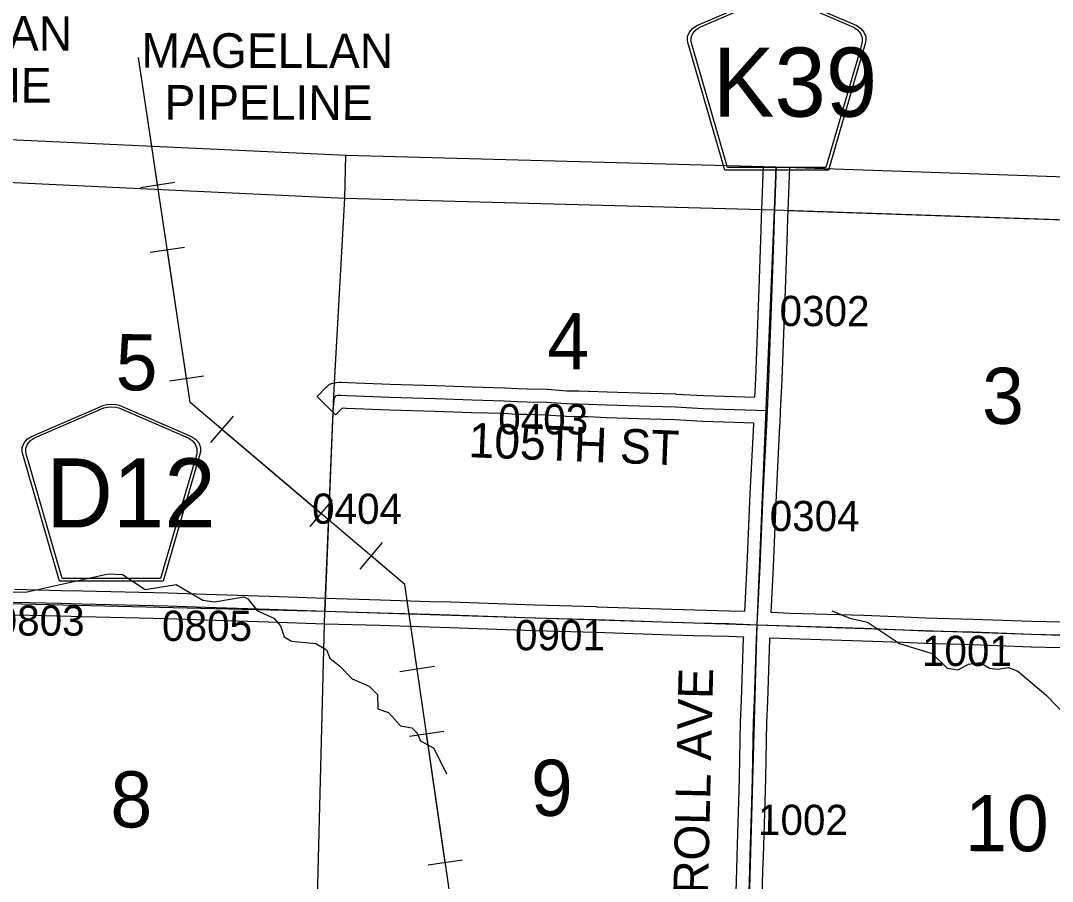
# Model space of a CAD drawing. Extents: x -157.2 to -99.3, y 12.2 to 46.2.
# Drawn here: x -143.15 to -140.761, y 39.474 to 41.468 of the extents above; entities that cross this region are included whole.
import ezdxf

# ---------------------------------------------------------------- set-up
doc = ezdxf.new("R2010")
doc.units = 0
for name, color, linetype in [('tdCoClipBndry', 7, 'Continuous'), ('tdCoCoBndry', 7, 'Continuous'), ('tdCoCoBndryPart', 7, 'Continuous'), ('tdCoHydroRiver', 7, 'Continuous'), ('tdCoPipe', 7, 'Continuous'), ('tdCoPipeTxt', 7, 'Continuous'), ('tdCoSecRdNmbr', 7, 'Continuous'), ('tdCoSecRdTxt', 7, 'Continuous'), ('tdCoSecRteBand', 7, 'Continuous'), ('tdCoSecRteCL', 7, 'Continuous'), ('tdCoSectLine', 7, 'Continuous'), ('tdCoSectLinePart', 7, 'Continuous'), ('tdCoSectNmbr', 7, 'Continuous'), ('tdCoShieldCoRte', 7, 'Continuous'), ('tdCoShieldCoRteHrd', 7, 'Continuous'), ('tdCoSurfAsphalt', 7, 'Continuous'), ('tdCoSurfGravel', 7, 'Continuous'), ('tdCoSurfLNO', 7, 'Continuous'), ('tdCoTwpBndryShd', 7, 'Continuous')]:
    doc.layers.add(name, color=color, linetype=linetype)

msp = doc.modelspace()

# ---------------------------------------------------------------- linework, layer by layer
at = {"layer": 'tdCoClipBndry'}
msp.add_lwpolyline([(-150.407, 41.4676), (-149.3946, 41.4438), (-148.3968, 41.411), (-147.4001, 41.3615), (-145.4135, 41.2969), (-142.396, 41.1563), (-141.4008, 41.1294), (-139.4104, 41.0607), (-138.4128, 41.0377), (-137.3849, 40.9986), (-130.3617, 40.7621)], dxfattribs=at)
at = {"layer": 'tdCoCoBndry'}
msp.add_lwpolyline([(-152.9518, 41.3883), (-152.409, 41.3796), (-151.4143, 41.374), (-150.4076, 41.3676), (-149.397, 41.3439), (-148.4001, 41.3111), (-147.4042, 41.2616), (-146.4159, 41.2271), (-145.4182, 41.197), (-144.4306, 41.151), (-143.3778, 41.1032), (-142.3996, 41.0564), (-141.4043, 41.0295), (-140.4086, 40.9954), (-139.4133, 40.9608), (-138.4166, 40.9378), (-137.3885, 40.8986), (-136.3904, 40.8656), (-135.3934, 40.8324), (-134.3958, 40.7988)], dxfattribs=at)
at = {"layer": 'tdCoCoBndryPart'}
for points in [[(-143.6171, 41.1141), (-143.3778, 41.1032), (-142.3996, 41.0564), (-141.4341, 41.0303)], [(-141.3742, 41.0285), (-140.4385, 40.9964)]]:
    msp.add_lwpolyline(points, dxfattribs=at)
at = {"layer": 'tdCoHydroRiver'}
for points in [[(-143.2296, 40.1435), (-143.1349, 40.1451), (-142.9472, 40.1863), (-142.9141, 40.1852), (-142.8616, 40.1504), (-142.7901, 40.1622), (-142.7282, 40.1255), (-142.7015, 40.1214), (-142.6332, 40.1334), (-142.6239, 40.1284), (-142.6012, 40.1008), (-142.5638, 40.0838), (-142.5487, 40.0659), (-142.54, 40.0404), (-142.523, 40.0304), (-142.4663, 40.0254), (-142.4416, 40.0103), (-142.4343, 39.9912), (-142.4112, 39.9731), (-142.3822, 39.9437), (-142.3433, 39.9266), (-142.3234, 39.9071), (-142.323, 39.8739), (-142.298, 39.8652), (-142.2706, 39.8343), (-142.2439, 39.8303), (-142.2317, 39.8173), (-142.2244, 39.7997), (-142.1934, 39.7829), (-142.1638, 39.7235)], [(-141.2719, 40.1013), (-141.2299, 40.0841), (-141.1892, 40.0749), (-141.115, 40.0251), (-141.04, 40.0022), (-141.0048, 39.9679), (-140.9797, 39.9639), (-140.9556, 39.9773), (-140.9286, 39.9811), (-140.907, 39.9678), (-140.8881, 39.9656), (-140.8627, 39.9695), (-140.8409, 39.9609), (-140.7764, 39.9067), (-140.7275, 39.8562)]]:
    msp.add_lwpolyline(points, dxfattribs=at)
at = {"layer": 'tdCoPipe'}
for p, q in [((-142.793, 41.0928), (-142.8725, 41.0809)), ((-142.7705, 40.9425), (-142.8501, 40.9306)), ((-142.7259, 40.6448), (-142.8054, 40.6329)), ((-142.6582, 40.5521), (-142.7103, 40.4906)), ((-142.4286, 40.3575), (-142.4807, 40.2961)), ((-142.3127, 40.2592), (-142.3648, 40.1977)), ((-142.1921, 39.9716), (-142.2717, 39.96)), ((-142.1703, 39.8211), (-142.25, 39.8095)), ((-142.127, 39.5233), (-142.2066, 39.5117))]:
    msp.add_line(p, q, dxfattribs=at)
for points in [[(-136.934, 22.5495), (-137.7242, 24.8933), (-138.4968, 27.1666), (-138.4114, 27.2635), (-138.4614, 27.8735), (-138.7227, 28.0895), (-138.7183, 28.4663), (-139.0397, 29.2926), (-139.1184, 29.8198), (-140.0614, 32.629), (-140.3902, 33.7747), (-140.3873, 34.3489), (-140.6033, 34.3601), (-141.0238, 35.5765), (-141.1818, 36.0085), (-141.3937, 37.236), (-141.4233, 37.6118), (-141.6227, 37.7022), (-142.0941, 39.016), (-142.2605, 40.1621), (-142.7574, 40.5833), (-142.8772, 41.3829)], [(-142.8328, 41.0869), (-142.8509, 41.2078)], [(-142.7657, 40.6389), (-142.8103, 40.9365)], [(-142.4547, 40.3267), (-142.6843, 40.5213)], [(-142.232, 39.9658), (-142.2605, 40.1621), (-142.3387, 40.2284)], [(-142.1669, 39.5175), (-142.2101, 39.8153)]]:
    msp.add_lwpolyline(points, dxfattribs=at)
at = {"layer": 'tdCoSecRteBand'}
for points in [[(-143.163, 40.151), (-143.0561, 40.1483), (-143.0072, 40.1471), (-142.8085, 40.1424), (-142.8083, 40.1424), (-142.8081, 40.1424), (-142.7211, 40.1394), (-142.5742, 40.135), (-142.5741, 40.135), (-142.574, 40.135), (-142.4438, 40.1301), (-142.3169, 40.1266), (-142.3168, 40.1266), (-142.3167, 40.1266), (-142.2018, 40.1229), (-142.1545, 40.1214), (-142.1544, 40.1214), (-142.1543, 40.1214), (-141.9594, 40.1145), (-141.817, 40.1106), (-141.8169, 40.1106), (-141.8168, 40.1105), (-141.6422, 40.1046), (-141.5901, 40.1029), (-141.5099, 40.1012), (-141.5096, 40.1012), (-141.5094, 40.1012), (-141.4733, 40.0998), (-141.4733, 40.1), (-141.4726, 40.1147), (-141.4726, 40.1148), (-141.4726, 40.1149), (-141.4679, 40.206), (-141.4608, 40.3718), (-141.4608, 40.372), (-141.4608, 40.3721), (-141.4527, 40.533), (-141.4525, 40.5357), (-141.4985, 40.537), (-141.4986, 40.537), (-141.4987, 40.537), (-141.5705, 40.5398), (-141.5707, 40.5398), (-141.571, 40.5398), (-141.6352, 40.5432), (-141.6939, 40.5447), (-141.6941, 40.5447), (-141.6942, 40.5447), (-141.7938, 40.5481), (-141.7939, 40.5481), (-141.794, 40.5481), (-141.8362, 40.5499), (-141.8587, 40.5501), (-141.859, 40.5501), (-141.8592, 40.5501), (-141.8873, 40.5508), (-141.888, 40.5509), (-141.8886, 40.5509), (-141.9338, 40.5541), (-141.979, 40.5553), (-142.0004, 40.5558), (-142.001, 40.5558), (-142.0016, 40.5558), (-142.0316, 40.5578), (-142.1055, 40.5595), (-142.1057, 40.5595), (-142.1059, 40.5595), (-142.1904, 40.5627), (-142.296, 40.5659), (-142.2962, 40.5659), (-142.2963, 40.5659), (-142.3954, 40.5696), (-142.3961, 40.5696), (-142.3967, 40.5697), (-142.4057, 40.5704), (-142.4211, 40.555), (-142.4635, 40.5974), (-142.4423, 40.6186), (-142.4404, 40.6205), (-142.4348, 40.6262), (-142.4271, 40.6283), (-142.4244, 40.629), (-142.422, 40.6297), (-142.4196, 40.6299), (-142.4124, 40.6307), (-142.4096, 40.6309), (-142.4069, 40.6307), (-142.3925, 40.6295), (-142.2941, 40.6259), (-142.1884, 40.6227), (-142.1883, 40.6227), (-142.1882, 40.6227), (-142.1038, 40.6195), (-142.0296, 40.6177), (-142.029, 40.6177), (-142.0284, 40.6177), (-141.9984, 40.6157), (-141.9776, 40.6153), (-141.9775, 40.6153), (-141.9774, 40.6153), (-141.9316, 40.614), (-141.9309, 40.614), (-141.9303, 40.614), (-141.8851, 40.6108), (-141.8578, 40.6101), (-141.8351, 40.6098), (-141.8347, 40.6098), (-141.8343, 40.6098), (-141.7917, 40.6081), (-141.6923, 40.6047), (-141.6332, 40.6032), (-141.6328, 40.6032), (-141.6324, 40.6031), (-141.568, 40.5997), (-141.4966, 40.597), (-141.4499, 40.5957), (-141.4499, 40.5961), (-141.448, 40.6391), (-141.4448, 40.7228), (-141.4402, 40.8476), (-141.4352, 40.9825), (-141.4345, 41.0135), (-141.4345, 41.0137), (-141.4345, 41.0139), (-141.4339, 41.0307), (-141.4302, 41.1302)], [(-141.3702, 41.1283), (-141.3739, 41.0285), (-141.3745, 41.0119), (-141.3753, 40.9809), (-141.3753, 40.9807), (-141.3753, 40.9805), (-141.3802, 40.8454), (-141.3802, 40.8454), (-141.3802, 40.8454), (-141.3848, 40.7206), (-141.3848, 40.7206), (-141.3848, 40.7206), (-141.388, 40.6367), (-141.388, 40.6366), (-141.388, 40.6366), (-141.3912, 40.5637), (-141.3921, 40.534), (-141.3925, 40.534), (-141.3927, 40.5303), (-141.3927, 40.5302), (-141.3927, 40.5301), (-141.4009, 40.3691), (-141.408, 40.2033), (-141.408, 40.2032), (-141.408, 40.203), (-141.4127, 40.1119), (-141.4133, 40.0975), (-141.368, 40.0958), (-141.198, 40.0908), (-141.1978, 40.0908), (-141.1976, 40.0908), (-141.1054, 40.0871), (-141.1053, 40.0871), (-141.1053, 40.0871), (-141.0547, 40.0849), (-140.945, 40.0819), (-140.9448, 40.0819), (-140.9447, 40.0819), (-140.809, 40.0768), (-140.6746, 40.0736)], [(-141.4966, 39.3458), (-141.4921, 39.5016), (-141.4921, 39.5018), (-141.4921, 39.5019), (-141.4909, 39.5338), (-141.4865, 39.6856), (-141.4857, 39.7145), (-141.483, 39.8437), (-141.483, 39.844), (-141.483, 39.8442), (-141.481, 39.894), (-141.4761, 40.0374), (-141.4761, 40.0376), (-141.4761, 40.0377), (-141.476, 40.0398), (-141.5114, 40.0412), (-141.5916, 40.0429), (-141.5917, 40.0429), (-141.5919, 40.0429), (-141.6442, 40.0447), (-141.6442, 40.0447), (-141.6442, 40.0447), (-141.8187, 40.0506), (-141.9612, 40.0545), (-141.9613, 40.0545), (-141.9614, 40.0545), (-142.1564, 40.0614), (-142.2037, 40.0629), (-142.2037, 40.0629), (-142.2037, 40.0629), (-142.3186, 40.0666), (-142.4456, 40.0701), (-142.4457, 40.0701), (-142.4459, 40.0701), (-142.5761, 40.075), (-142.723, 40.0794), (-142.7231, 40.0794), (-142.7231, 40.0794), (-142.81, 40.0824), (-143.0086, 40.0871), (-143.0087, 40.0871), (-143.0087, 40.0871), (-143.0576, 40.0883), (-143.1644, 40.091)], [(-140.6763, 40.0136), (-140.8106, 40.0168), (-140.8109, 40.0168), (-140.8111, 40.0168), (-140.9468, 40.022), (-141.0566, 40.0249), (-141.0568, 40.0249), (-141.0571, 40.0249), (-141.1078, 40.0272), (-141.1999, 40.0309), (-141.3698, 40.0358), (-141.37, 40.0358), (-141.3701, 40.0358), (-141.4158, 40.0375), (-141.416, 40.0375), (-141.4161, 40.0352), (-141.4211, 39.8918), (-141.4211, 39.8918), (-141.4211, 39.8917), (-141.423, 39.8422), (-141.4257, 39.7132), (-141.4257, 39.7131), (-141.4257, 39.7131), (-141.4265, 39.684), (-141.4265, 39.6839), (-141.4265, 39.6839), (-141.4309, 39.532), (-141.4309, 39.5318), (-141.4309, 39.5317), (-141.4322, 39.4998), (-141.4366, 39.3442)]]:
    msp.add_lwpolyline(points, dxfattribs=at)
at = {"layer": 'tdCoSecRteCL'}
for points in [[(-141.4212, 40.5648), (-141.418, 40.6379), (-141.4148, 40.7217), (-141.4102, 40.8465), (-141.4053, 40.9816), (-141.4045, 41.0128), (-141.4039, 41.0296), (-141.4002, 41.1294)], [(-142.4211, 40.5974), (-142.4192, 40.5993), (-142.4165, 40.6001), (-142.4093, 40.6008), (-142.3943, 40.5996), (-142.2951, 40.5959), (-142.1893, 40.5927), (-142.1048, 40.5895), (-142.0303, 40.5877), (-141.9997, 40.5858), (-141.9783, 40.5853), (-141.9324, 40.584), (-141.8865, 40.5808), (-141.8584, 40.5801), (-141.8355, 40.5798), (-141.7928, 40.5781), (-141.6932, 40.5747), (-141.634, 40.5732), (-141.5694, 40.5697), (-141.4976, 40.567), (-141.4212, 40.5648)], [(-141.4447, 40.0687), (-141.4427, 40.1133), (-141.438, 40.2046), (-141.4308, 40.3706), (-141.4227, 40.5316), (-141.4212, 40.5648)], [(-143.685, 40.1302), (-143.6617, 40.1294), (-143.5707, 40.1284), (-143.4535, 40.1245), (-143.3527, 40.1222), (-143.2772, 40.1227), (-143.1638, 40.121), (-143.0569, 40.1183), (-143.0079, 40.1171), (-142.8092, 40.1124), (-142.7221, 40.1094), (-142.5751, 40.105), (-142.4447, 40.1001), (-142.3177, 40.0966), (-142.2028, 40.0929), (-142.1554, 40.0914), (-141.9603, 40.0845), (-141.8178, 40.0806), (-141.6432, 40.0746), (-141.5909, 40.0729), (-141.5105, 40.0712), (-141.4447, 40.0687)], [(-141.472, 39.0694), (-141.4705, 39.1449), (-141.4695, 39.2088), (-141.4666, 39.3449), (-141.4621, 39.5008), (-141.4609, 39.5328), (-141.4565, 39.6847), (-141.4557, 39.7138), (-141.453, 39.8431), (-141.451, 39.8929), (-141.4461, 40.0364), (-141.4447, 40.0687)], [(-141.4447, 40.0687), (-141.369, 40.0658), (-141.1988, 40.0608), (-141.1066, 40.0571), (-141.0558, 40.0549), (-140.9458, 40.052), (-140.8099, 40.0468), (-140.6753, 40.0436), (-140.5855, 40.0394), (-140.5108, 40.0362), (-140.4583, 40.0344), (-140.4469, 40.0343)]]:
    msp.add_lwpolyline(points, dxfattribs=at)
at = {"layer": 'tdCoSectLine'}
for points in [[(-142.3996, 41.0564), (-142.3967, 41.1563)], [(-141.4043, 41.0295), (-141.4005, 41.1294)], [(-143.3778, 41.1032), (-142.3996, 41.0564)], [(-142.4455, 40.1001), (-142.425, 40.6004), (-142.3996, 41.0564)], [(-142.3996, 41.0564), (-141.4043, 41.0295)], [(-141.445, 40.0687), (-141.4043, 41.0295)], [(-141.4043, 41.0295), (-140.4086, 40.9954)], [(-143.4354, 40.1241), (-142.4455, 40.1001)], [(-142.4709, 39.1056), (-142.4455, 40.1001)], [(-142.4455, 40.1001), (-141.445, 40.0687)], [(-141.4724, 39.0694), (-141.445, 40.0687)], [(-141.445, 40.0687), (-140.4473, 40.0343)]]:
    msp.add_lwpolyline(points, dxfattribs=at)
at = {"layer": 'tdCoSectLinePart'}
for points in [[(-142.3996, 41.0564), (-142.3967, 41.1563)], [(-143.3778, 41.1032), (-142.3996, 41.0564)], [(-142.4234, 40.6292), (-142.3996, 41.0564)], [(-142.3996, 41.0564), (-141.4341, 41.0303)], [(-141.3742, 41.0285), (-140.4385, 40.9964)], [(-142.4443, 40.1304), (-142.4267, 40.5592)], [(-142.4702, 39.1356), (-142.4463, 40.0705)]]:
    msp.add_lwpolyline(points, dxfattribs=at)
at = {"layer": 'tdCoShieldCoRte'}
for points in [[(-141.5193, 41.1212), (-141.6013, 41.4041), (-141.6051, 41.4173), (-141.6059, 41.4232), (-141.6059, 41.431), (-141.6016, 41.4413), (-141.5944, 41.4498), (-141.5848, 41.4564), (-141.4175, 41.5288), (-141.41, 41.5304), (-141.3996, 41.5313), (-141.3891, 41.5304), (-141.3816, 41.5288), (-141.2143, 41.4564), (-141.2048, 41.4498), (-141.1975, 41.4413), (-141.1933, 41.431), (-141.1933, 41.4232), (-141.194, 41.4173), (-141.1979, 41.4041), (-141.2798, 41.1212)], [(-141.5135, 41.1276), (-141.5932, 41.4028), (-141.5969, 41.4155), (-141.5976, 41.4211), (-141.5976, 41.4286), (-141.5935, 41.4385), (-141.5866, 41.4467), (-141.5774, 41.4531), (-141.4168, 41.5225), (-141.4096, 41.5241), (-141.3996, 41.525), (-141.3896, 41.5241), (-141.3823, 41.5225), (-141.2218, 41.4531), (-141.2126, 41.4467), (-141.2056, 41.4385), (-141.2015, 41.4286), (-141.2015, 41.4211), (-141.2022, 41.4155), (-141.2059, 41.4028), (-141.2857, 41.1276)]]:
    msp.add_lwpolyline(points, close=True, dxfattribs=at)
at = {"layer": 'tdCoShieldCoRteHrd'}
for points in [[(-143.0596, 40.1697), (-143.1415, 40.4526), (-143.1454, 40.4658), (-143.1461, 40.4717), (-143.1461, 40.4795), (-143.1419, 40.4898), (-143.1346, 40.4983), (-143.125, 40.505), (-142.9577, 40.5773), (-142.9502, 40.5789), (-142.9398, 40.5799), (-142.9294, 40.5789), (-142.9219, 40.5773), (-142.7546, 40.505), (-142.745, 40.4983), (-142.7377, 40.4898), (-142.7335, 40.4795), (-142.7335, 40.4717), (-142.7342, 40.4658), (-142.7381, 40.4526), (-142.82, 40.1697)], [(-143.0537, 40.1761), (-143.1334, 40.4513), (-143.1372, 40.464), (-143.1379, 40.4696), (-143.1379, 40.4771), (-143.1338, 40.487), (-143.1268, 40.4952), (-143.1176, 40.5016), (-142.957, 40.571), (-142.9498, 40.5726), (-142.9398, 40.5735), (-142.9298, 40.5726), (-142.9226, 40.571), (-142.762, 40.5016), (-142.7528, 40.4952), (-142.7458, 40.487), (-142.7417, 40.4771), (-142.7417, 40.4696), (-142.7424, 40.464), (-142.7462, 40.4513), (-142.8259, 40.1761)]]:
    msp.add_lwpolyline(points, close=True, dxfattribs=at)
at = {"layer": 'tdCoSurfAsphalt'}
for points in [[(-144.4527, 40.1488), (-144.4397, 40.1479), (-144.346, 40.1452), (-144.3221, 40.1452), (-144.1855, 40.1415), (-144.1008, 40.1397), (-144.0082, 40.1378), (-143.9447, 40.1361), (-143.8871, 40.1346), (-143.8279, 40.1336), (-143.7394, 40.1321), (-143.685, 40.1302), (-143.6617, 40.1294), (-143.5707, 40.1284), (-143.4535, 40.1245), (-143.3527, 40.1222), (-143.2772, 40.1227), (-143.1638, 40.121), (-143.0569, 40.1183)], [(-143.0569, 40.1183), (-143.0079, 40.1171), (-142.8092, 40.1124), (-142.7221, 40.1094), (-142.5751, 40.105), (-142.4447, 40.1001), (-142.3177, 40.0966), (-142.2028, 40.0929), (-142.1554, 40.0914), (-141.9603, 40.0845), (-141.8178, 40.0806), (-141.6432, 40.0746), (-141.5909, 40.0729), (-141.5105, 40.0712), (-141.4447, 40.0687), (-141.369, 40.0658), (-141.1988, 40.0608), (-141.1066, 40.0571), (-141.0558, 40.0549), (-140.9458, 40.052), (-140.8099, 40.0468), (-140.6753, 40.0436)]]:
    msp.add_lwpolyline(points, dxfattribs=at)
at = {"layer": 'tdCoSurfGravel'}
for p, q in [((-141.4039, 41.0296), (-141.4002, 41.1294)), ((-141.4045, 41.0128), (-141.4039, 41.0296))]:
    msp.add_line(p, q, dxfattribs=at)
for points in [[(-141.4447, 40.0687), (-141.4427, 40.1133), (-141.438, 40.2046), (-141.4308, 40.3706), (-141.4227, 40.5316), (-141.4212, 40.5648), (-141.418, 40.6379), (-141.4148, 40.7217), (-141.4102, 40.8465), (-141.4053, 40.9816), (-141.4045, 41.0128)], [(-142.4211, 40.5974), (-142.4192, 40.5993), (-142.4165, 40.6001), (-142.4093, 40.6008), (-142.3943, 40.5996), (-142.2951, 40.5959), (-142.1893, 40.5927), (-142.1048, 40.5895), (-142.0303, 40.5877), (-141.9997, 40.5858), (-141.9783, 40.5853), (-141.9324, 40.584), (-141.8865, 40.5808), (-141.8584, 40.5801), (-141.8355, 40.5798), (-141.7928, 40.5781), (-141.6932, 40.5747), (-141.634, 40.5732), (-141.5694, 40.5697), (-141.4976, 40.567), (-141.4212, 40.5648)], [(-141.4666, 39.3449), (-141.4621, 39.5008), (-141.4609, 39.5328), (-141.4565, 39.6847), (-141.4557, 39.7138), (-141.453, 39.8431), (-141.451, 39.8929), (-141.4461, 40.0364), (-141.4447, 40.0687)]]:
    msp.add_lwpolyline(points, dxfattribs=at)
at = {"layer": 'tdCoSurfLNO'}
for q in [(-142.4211, 40.5974), (-142.4214, 40.5971)]:
    msp.add_line((-142.4214, 40.5971), q, dxfattribs=at)
msp.add_lwpolyline([(-142.4447, 40.1001), (-142.4261, 40.5609), (-142.4246, 40.5811), (-142.4241, 40.5882), (-142.4231, 40.5937), (-142.4214, 40.5971)], dxfattribs=at)
at = {"layer": 'tdCoTwpBndryShd'}
msp.add_lwpolyline([(-150.4076, 41.3676), (-149.397, 41.3439), (-148.4001, 41.3111), (-147.4042, 41.2616), (-146.4159, 41.2271), (-145.4182, 41.197), (-144.4306, 41.151), (-143.3778, 41.1032), (-142.3996, 41.0564), (-141.4043, 41.0295), (-140.4086, 40.9954), (-139.4133, 40.9608), (-138.4166, 40.9378), (-137.3885, 40.8986), (-136.3904, 40.8656), (-135.3934, 40.8324), (-134.3958, 40.7988)], dxfattribs=at)

# ---------------------------------------------------------------- texts
at = {"layer": 'tdCoPipeTxt'}
for s, rotation, p in [('MAGELLAN', 359.8907, (-143.6133, 41.3992)), ('MAGELLAN', 359.8912, (-142.8701, 41.359)), ('PIPELINE', 359.8907, (-143.5601, 41.2791)), ('PIPELINE', 359.8912, (-142.8169, 41.2388))]:
    msp.add_text(s, height=0.08, rotation=rotation, dxfattribs=at).set_placement(p)
at = {"layer": 'tdCoSecRdNmbr'}
for s, rotation, p in [('0302', 359.8919, (-141.393, 40.7605)), ('0403', 359.8915, (-142.0443, 40.5098)), ('0404', 359.8897, (-142.4753, 40.3026)), ('0304', 359.8919, (-141.4159, 40.2857)), ('0803', 359.8907, (-143.2101, 40.0437)), ('0901', 359.8915, (-142.0055, 40.0096)), ('1001', 359.8922, (-141.0633, 39.9734)), ('1002', 359.8919, (-141.4429, 39.582))]:
    msp.add_text(s, height=0.07, rotation=rotation, dxfattribs=at).set_placement(p)
msp.add_text('0805', height=0.07, dxfattribs=at).set_placement((-142.8225, 40.0312))
at = {"layer": 'tdCoSecRdTxt'}
for s, rotation, p in [('105TH ST', 357.7598, (-142.1141, 40.4569)), ('CARROLL AVE', 88.641, (-141.5642, 39.2185))]:
    msp.add_text(s, height=0.08, rotation=rotation, dxfattribs=at).set_placement(p)
at = {"layer": 'tdCoSectNmbr'}
for s, rotation, p in [('4', 359.8915, (-141.9305, 40.6605)), ('5', 359.8908, (-142.9299, 40.6118)), ('3', 359.8922, (-140.9241, 40.534)), ('9', 359.8915, (-141.9686, 39.6261)), ('8', 359.8907, (-142.9421, 39.5993)), ('10', 359.8923, (-140.9634, 39.5443))]:
    msp.add_text(s, height=0.13, rotation=rotation, dxfattribs=at).set_placement(p)
at = {"layer": 'tdCoShieldCoRte'}
msp.add_text('K39', height=0.16, dxfattribs=at).set_placement((-141.5475, 41.2455))
at = {"layer": 'tdCoShieldCoRteHrd'}
msp.add_text('D12', height=0.16, dxfattribs=at).set_placement((-143.0908, 40.294))

doc.saveas('drawing.dxf')
